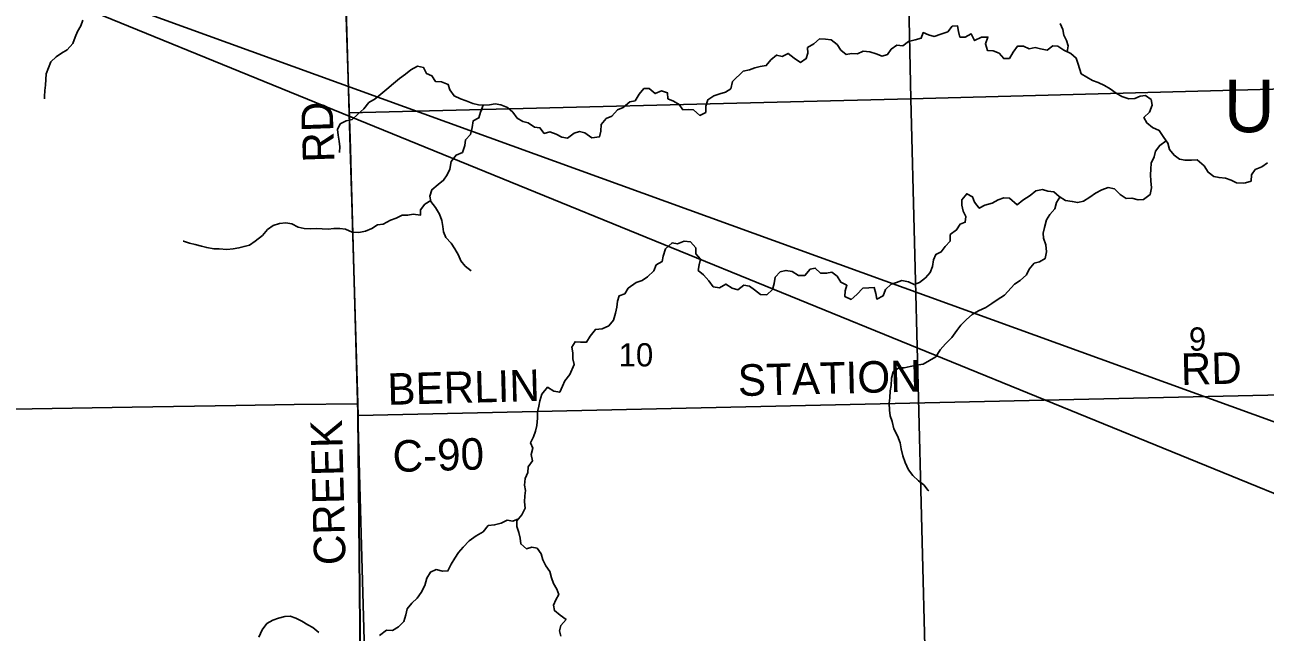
# Model space of a CAD drawing. Extents: x 0 to 34, y 0 to 22.
# Drawn here: x 6.705 to 8.938, y 16.179 to 17.274 of the extents above; entities that cross this region are included whole.
import ezdxf

# ---------------------------------------------------------------- set-up
doc = ezdxf.new("R2010")
doc.units = 0
for name, color, linetype in [('GM_X_Corporation', 7, 'Continuous'), ('GM_X_County_Road', 7, 'Continuous'), ('GM_X_County_Road_Text', 7, 'Continuous'), ('GM_X_Minor_Lake_Text', 7, 'Continuous'), ('GM_X_Minor_River', 7, 'Continuous'), ('GM_X_Section_Text', 7, 'Continuous'), ('GM_X_Township_Road', 7, 'Continuous'), ('SH_Text', 7, 'Continuous')]:
    doc.layers.add(name, color=color, linetype=linetype)

msp = doc.modelspace()

# ---------------------------------------------------------------- linework, layer by layer
at = {"layer": 'GM_X_Corporation'}
for points in [[(7.283, 17.3071), (7.2872, 17.1772), (7.2911, 17.0516), (7.2943, 16.935), (7.2998, 16.7507), (7.3046, 16.5913), (7.3049, 16.5704), (7.3097, 16.0633), (7.3129, 15.9614), (7.3375, 15.0689), (8.3803, 15.0917), (8.8365, 15.1033), (9.7895, 15.1275), (9.7895, 20.2375)], [(2.9895, 20.1176), (2.9895, 14.989), (3.1061, 14.9902), (3.7218, 15.0051), (5.1362, 15.0301), (5.7825, 15.0418), (6.0746, 15.0468), (7.3134, 15.0684), (7.3375, 15.0689), (7.3129, 15.9614), (7.3097, 16.0633), (7.3049, 16.5704), (7.3046, 16.5913), (7.2998, 16.7507), (7.2943, 16.935), (7.2911, 17.0516), (7.2872, 17.1772), (7.283, 17.3071)]]:
    msp.add_lwpolyline(points, dxfattribs=at)
for points in [[(9.2853, 18.1891), (9.3117, 17.1675), (8.3006, 17.1406), (8.2786, 18.1687)], [(8.2786, 18.1687), (8.3006, 17.1406), (7.2894, 17.115), (7.2759, 17.5735), (7.2643, 18.1469)], [(9.3117, 17.1675), (9.3404, 16.1359), (8.3266, 16.1074), (8.3006, 17.1406)], [(8.3006, 17.1406), (8.3266, 16.1074), (7.3183, 16.0795), (7.3111, 16.3358), (7.2941, 16.9623), (7.2894, 17.115)]]:
    msp.add_lwpolyline(points, close=True, dxfattribs=at)
at = {"layer": 'GM_X_County_Road'}
for points in [[(7.3099, 16.0628), (7.3051, 16.5699), (7.3048, 16.5907), (7.3, 16.7502), (7.2945, 16.9345), (7.2913, 17.051), (7.2874, 17.1766), (7.2832, 17.3066), (7.2801, 17.4169), (7.2766, 17.5196), (7.2753, 17.5759), (7.2469, 19.0552)], [(7.3051, 16.5699), (8.9434, 16.6067), (9.1022, 16.6101), (9.3888, 16.6198), (9.477, 16.6223), (9.5999, 16.6258), (9.7209, 16.6324), (9.7895, 16.6343)]]:
    msp.add_lwpolyline(points, dxfattribs=at)
at = {"layer": 'GM_X_Minor_River'}
for points in [[(6.8096, 17.2819), (6.8059, 17.2716), (6.7999, 17.2617), (6.7958, 17.2514), (6.7913, 17.2399), (6.7812, 17.2288), (6.7713, 17.2227), (6.7615, 17.2161), (6.7517, 17.2069), (6.748, 17.1959), (6.7435, 17.1852), (6.7432, 17.1753), (6.7422, 17.165), (6.7411, 17.1555), (6.7404, 17.1445), (6.7405, 17.1403)], [(8.8994, 16.9881), (8.8869, 16.9887), (8.877, 16.9935), (8.8667, 16.9976), (8.8553, 16.9983), (8.8457, 17.0005), (8.8358, 17.008), (8.8288, 17.0194), (8.8162, 17.0303), (8.8059, 17.0298), (8.7941, 17.0297), (8.7842, 17.0319), (8.7743, 17.0387), (8.7658, 17.0489), (8.7631, 17.0603), (8.7561, 17.0709), (8.7476, 17.083), (8.7354, 17.0886), (8.7251, 17.0968), (8.7201, 17.1067), (8.7299, 17.1166), (8.7347, 17.1292), (8.7331, 17.1391), (8.7231, 17.1466), (8.7132, 17.1454), (8.7034, 17.1411), (8.6928, 17.1403), (8.6805, 17.1448), (8.6698, 17.1504), (8.6595, 17.1583), (8.6488, 17.1643), (8.6374, 17.1695), (8.6274, 17.1736), (8.6068, 17.1856), (8.6017, 17.203), (8.5982, 17.2137), (8.5886, 17.2223), (8.5756, 17.2279), (8.5653, 17.2351), (8.5558, 17.2357), (8.5456, 17.2281), (8.5341, 17.2303), (8.5242, 17.2328), (8.5132, 17.2305), (8.5033, 17.235), (8.4922, 17.2352), (8.4847, 17.2245), (8.478, 17.2131), (8.4677, 17.213), (8.4593, 17.2228), (8.4486, 17.2269), (8.4387, 17.2272), (8.4348, 17.2397), (8.4392, 17.2515), (8.4278, 17.2515), (8.4153, 17.2453), (8.4091, 17.2574), (8.3985, 17.2516), (8.3887, 17.2515), (8.3863, 17.2618), (8.3843, 17.272), (8.3748, 17.2712), (8.3669, 17.2609), (8.3544, 17.257), (8.3426, 17.2527), (8.3323, 17.2556), (8.3228, 17.2597), (8.3191, 17.2495), (8.3084, 17.2467), (8.2963, 17.2439), (8.2857, 17.2359), (8.2754, 17.2369), (8.2652, 17.2296), (8.2585, 17.2201), (8.249, 17.2173), (8.2379, 17.2214), (8.2265, 17.2248), (8.2147, 17.2262), (8.2045, 17.2212), (8.1934, 17.2218), (8.1839, 17.2202), (8.1743, 17.2282), (8.1678, 17.238), (8.1567, 17.2466), (8.1468, 17.2477), (8.1358, 17.2484), (8.1256, 17.2396), (8.1146, 17.2326), (8.1151, 17.2227), (8.1121, 17.2128), (8.1015, 17.2059), (8.0904, 17.2138), (8.0797, 17.2221), (8.0687, 17.2167), (8.0588, 17.2193), (8.0486, 17.2104), (8.04, 17.2001), (8.0293, 17.1985), (8.0195, 17.1961), (8.01, 17.1926), (7.9986, 17.1899)], [(8.5816, 17.2253), (8.5835, 17.2356), (8.5804, 17.2454), (8.5757, 17.2553), (8.5741, 17.2655), (8.5691, 17.2758)], [(7.9986, 17.1899), (7.979, 17.1715), (7.9764, 17.1585), (7.9666, 17.1524), (7.9563, 17.1496), (7.9457, 17.1458), (7.9348, 17.1388), (7.9314, 17.1274), (7.9312, 17.116), (7.9206, 17.1106), (7.9091, 17.1204), (7.8995, 17.1211), (7.89, 17.1206), (7.8835, 17.1304), (7.8728, 17.1361), (7.8629, 17.1405), (7.862, 17.1512), (7.8513, 17.1549), (7.8403, 17.1499), (7.8292, 17.1589), (7.8197, 17.1592), (7.8111, 17.1485), (7.8039, 17.137), (7.7945, 17.1347), (7.7827, 17.1247), (7.7725, 17.1204), (7.7623, 17.1093), (7.7521, 17.1047), (7.7431, 17.094), (7.7424, 17.0822), (7.7399, 17.0719), (7.7262, 17.0699), (7.7135, 17.0793), (7.7036, 17.0815), (7.6942, 17.0784), (7.6821, 17.0695), (7.6722, 17.0714), (7.6618, 17.0766), (7.6504, 17.0811), (7.6405, 17.0779), (7.6325, 17.0881), (7.6229, 17.0892), (7.6111, 17.0971), (7.6015, 17.0997), (7.5916, 17.1057), (7.5835, 17.1163), (7.5739, 17.1249), (7.5621, 17.1294), (7.5522, 17.1312), (7.542, 17.1296), (7.5313, 17.1288), (7.5218, 17.1298), (7.5115, 17.132), (7.4997, 17.1365), (7.4894, 17.1402), (7.4779, 17.1458), (7.4702, 17.1564), (7.4675, 17.1659), (7.4553, 17.1711), (7.4446, 17.1714), (7.438, 17.182), (7.4285, 17.1857), (7.4231, 17.1967), (7.412, 17.1989), (7.4003, 17.1923), (7.3905, 17.1847), (7.3799, 17.177), (7.3689, 17.1678), (7.3569, 17.1578), (7.3463, 17.1486), (7.3361, 17.1405), (7.3247, 17.1336), (7.3153, 17.1221), (7.3048, 17.1129), (7.2946, 17.1033), (7.2836, 17.1006), (7.273, 17.0952), (7.2681, 17.0852), (7.2694, 17.075), (7.2713, 17.064), (7.2726, 17.0541), (7.2719, 17.0442), (7.2715, 17.0435)], [(7.5305, 17.1289), (7.5257, 17.1166), (7.5224, 17.1059), (7.5125, 17.1009), (7.5107, 17.0887), (7.5074, 17.0761), (7.4988, 17.0666), (7.4973, 17.0563), (7.4929, 17.0437), (7.4815, 17.039), (7.4725, 17.0272), (7.4703, 17.0139), (7.4655, 17.0032), (7.4591, 16.9936), (7.4493, 16.986), (7.4379, 16.9764), (7.4346, 16.9649), (7.4362, 16.9554), (7.4447, 16.9445), (7.452, 16.9324), (7.4559, 16.921), (7.4579, 16.9104), (7.4588, 16.9005), (7.4634, 16.8903), (7.473, 16.8801), (7.4792, 16.8703), (7.4861, 16.8589), (7.49, 16.8487), (7.4981, 16.8389), (7.5085, 16.8306)], [(8.7601, 17.0648), (8.7486, 17.0564), (8.7411, 17.046), (8.7382, 17.0361), (8.7333, 17.0247), (8.7323, 17.0137), (8.7316, 17.0034), (8.7325, 16.9924), (8.7337, 16.9798), (8.7312, 16.9677), (8.7194, 16.9592), (8.7096, 16.9584), (8.6985, 16.9613), (8.6882, 16.9608), (8.6775, 16.968), (8.6668, 16.9782), (8.6554, 16.9807), (8.644, 16.9761), (8.6326, 16.9703), (8.6228, 16.963), (8.6115, 16.9561), (8.6008, 16.9533), (8.5909, 16.9555), (8.5787, 16.9573), (8.5673, 16.9641), (8.5577, 16.9727), (8.547, 16.9742), (8.5375, 16.9768), (8.5253, 16.9744), (8.5151, 16.9663), (8.5023, 16.9578), (8.4917, 16.9494), (8.4779, 16.9615), (8.4676, 16.9618), (8.4578, 16.9583), (8.4468, 16.9521), (8.4339, 16.9486), (8.4237, 16.9432), (8.4152, 16.9541), (8.4113, 16.964), (8.401, 16.9692), (8.3924, 16.9585), (8.3921, 16.949), (8.3948, 16.938), (8.3995, 16.9281), (8.3984, 16.9179), (8.3889, 16.9148), (8.3826, 16.9041), (8.3709, 16.8956), (8.371, 16.8838), (8.3623, 16.8743), (8.3552, 16.8647), (8.3453, 16.8601), (8.3412, 16.8501), (8.3394, 16.8383), (8.3353, 16.8277), (8.327, 16.8181), (8.3161, 16.8093), (8.3062, 16.8058), (8.2959, 16.8106), (8.2841, 16.8128), (8.2746, 16.8097), (8.2648, 16.8066), (8.255, 16.7966), (8.2505, 16.7856), (8.2391, 16.7794), (8.2375, 16.7896), (8.2344, 16.8003), (8.2245, 16.7998), (8.2139, 16.799), (8.2033, 16.7878), (8.1927, 16.779), (8.1817, 16.7839), (8.1823, 16.7941), (8.1853, 16.8044), (8.1742, 16.81), (8.168, 16.8206), (8.1581, 16.8278), (8.1486, 16.8262), (8.1379, 16.8261), (8.1284, 16.8355), (8.1189, 16.8332), (8.1098, 16.8221), (8.0984, 16.822), (8.0866, 16.8291), (8.0755, 16.8313), (8.0653, 16.8286), (8.0562, 16.819), (8.0541, 16.8076), (8.0515, 16.7965), (8.0409, 16.7869), (8.0299, 16.788), (8.0192, 16.7959), (8.0096, 16.803), (7.9997, 16.8045), (7.9887, 16.7964), (7.9788, 16.799), (7.9673, 16.8065), (7.956, 16.7999), (7.9446, 16.8014), (7.9369, 16.8123)], [(8.9424, 17.0248), (8.9323, 17.0178), (8.9206, 17.0131), (8.914, 17.0035), (8.913, 16.9921), (8.9032, 16.9889), (8.8994, 16.9881)], [(7.4359, 16.9572), (7.4256, 16.9504), (7.4173, 16.9405), (7.4178, 16.931), (7.4041, 16.9324), (7.3946, 16.9308), (7.3843, 16.9307), (7.3737, 16.9253), (7.3635, 16.9218), (7.3506, 16.9145), (7.3404, 16.9136), (7.3302, 16.9067), (7.3184, 16.9017), (7.3066, 16.8997), (7.2948, 16.9003), (7.2823, 16.9056), (7.2724, 16.9066), (7.2617, 16.9069), (7.2514, 16.9053), (7.2404, 16.9064), (7.2301, 16.907), (7.2187, 16.9062), (7.2081, 16.9065), (7.197, 16.9094), (7.1859, 16.9151), (7.1749, 16.9169), (7.1635, 16.916), (7.1525, 16.9121), (7.1423, 16.9048), (7.1329, 16.8941), (7.1197, 16.8837), (7.1095, 16.8768), (7.1, 16.8745), (7.0905, 16.8717), (7.0802, 16.8701), (7.0688, 16.8689), (7.0551, 16.8699), (7.0456, 16.8702), (7.0327, 16.8724), (7.0231, 16.875), (7.0121, 16.8779), (7.0014, 16.8805), (6.9907, 16.8838), (6.99, 16.8838)], [(8.5685, 16.9633), (8.5624, 16.9534), (8.5595, 16.9423), (8.5508, 16.932), (8.5448, 16.9221), (8.5408, 16.9084), (8.5386, 16.8985), (8.539, 16.889), (8.5437, 16.8772), (8.5446, 16.8647), (8.542, 16.8525), (8.5322, 16.8467), (8.5227, 16.844), (8.5137, 16.8336), (8.5088, 16.8233), (8.4971, 16.813), (8.4869, 16.8064), (8.4688, 16.7865), (8.4559, 16.7781), (8.4461, 16.7715), (8.4355, 16.7646), (8.4223, 16.7584), (8.4109, 16.7515), (8.4004, 16.7427), (8.3902, 16.7323), (8.3834, 16.7228), (8.374, 16.7101), (8.3627, 16.6987), (8.3529, 16.6883), (8.3454, 16.6757), (8.3337, 16.6688), (8.3223, 16.6622), (8.3106, 16.6606), (8.2992, 16.6582), (8.2882, 16.6559), (8.2787, 16.6554), (8.2688, 16.6485), (8.2655, 16.6371), (8.2649, 16.6238), (8.263, 16.6142), (8.2628, 16.6017), (8.2613, 16.5922), (8.2618, 16.5793), (8.2634, 16.569), (8.2666, 16.5588), (8.2697, 16.5459), (8.2763, 16.5334), (8.2814, 16.5205), (8.283, 16.5099), (8.2857, 16.497), (8.2904, 16.4852), (8.2962, 16.472), (8.3039, 16.4614), (8.3139, 16.4523), (8.3235, 16.4448), (8.3316, 16.4346), (8.3319, 16.4361)], [(7.9369, 16.8123), (7.9269, 16.8233), (7.9173, 16.8312), (7.9195, 16.8415), (7.9217, 16.8514), (7.9132, 16.8612), (7.9131, 16.8718), (7.9039, 16.8824), (7.8925, 16.8838), (7.8804, 16.8788), (7.8705, 16.881), (7.8588, 16.8699), (7.8543, 16.8569), (7.8525, 16.847), (7.8419, 16.8412), (7.8374, 16.8302), (7.8265, 16.8194), (7.8167, 16.8133), (7.8061, 16.8094), (7.7917, 16.799), (7.7853, 16.7891), (7.7751, 16.7856), (7.7725, 16.7757), (7.7711, 16.765), (7.7689, 16.7544), (7.7652, 16.7414), (7.7565, 16.7311), (7.7448, 16.726), (7.7326, 16.7248), (7.7232, 16.7126), (7.7165, 16.7022), (7.7058, 16.7022), (7.6959, 16.7028), (7.6899, 16.6929), (7.6916, 16.6827), (7.692, 16.672), (7.6944, 16.6618), (7.6866, 16.6435), (7.6775, 16.6324), (7.6734, 16.6225), (7.6682, 16.6118), (7.6575, 16.6136), (7.6465, 16.6207), (7.6363, 16.6085), (7.6322, 16.5959), (7.6304, 16.5864), (7.6282, 16.5761), (7.6283, 16.5647), (7.6269, 16.5518), (7.6243, 16.5415), (7.621, 16.5316), (7.6158, 16.5205), (7.6197, 16.5107), (7.6167, 16.4996), (7.6191, 16.4879), (7.6116, 16.4772), (7.6105, 16.4669), (7.6057, 16.4562), (7.6047, 16.444), (7.6063, 16.4345), (7.6056, 16.425), (7.6045, 16.4144), (7.6058, 16.403), (7.5998, 16.3908), (7.5911, 16.3801), (7.5909, 16.3698), (7.5947, 16.3592), (7.5967, 16.3486), (7.598, 16.3383), (7.6083, 16.3296), (7.6178, 16.3324), (7.6273, 16.3309), (7.6346, 16.3207), (7.6378, 16.3097), (7.6432, 16.2988), (7.6505, 16.2886), (7.6533, 16.2772), (7.6568, 16.2673), (7.663, 16.2571), (7.6665, 16.2472), (7.6612, 16.2377), (7.6568, 16.2278), (7.6587, 16.2183), (7.6691, 16.21), (7.6798, 16.2021), (7.6704, 16.1914), (7.6678, 16.1819), (7.6702, 16.172)], [(7.5941, 16.3837), (7.5839, 16.3792), (7.5736, 16.3811), (7.563, 16.376), (7.5509, 16.3725), (7.5395, 16.3717), (7.5305, 16.3602), (7.518, 16.3529), (7.5051, 16.344), (7.4942, 16.3325), (7.4859, 16.323), (7.4795, 16.313), (7.4728, 16.302), (7.4668, 16.2897), (7.4573, 16.2893), (7.4459, 16.2922), (7.4356, 16.2876), (7.4289, 16.2765), (7.4256, 16.2636), (7.4188, 16.251), (7.4117, 16.2407), (7.4019, 16.2318), (7.3936, 16.2215), (7.3911, 16.2105), (7.3874, 16.1986), (7.3779, 16.1887), (7.3673, 16.1825), (7.3563, 16.1828), (7.3438, 16.1732)], [(7.2346, 16.1788), (7.2239, 16.1878), (7.2144, 16.1923), (7.2037, 16.1991), (7.1933, 16.2047), (7.183, 16.2084), (7.1732, 16.2076), (7.1621, 16.2048), (7.1515, 16.2009), (7.1406, 16.1948), (7.1323, 16.1833), (7.1263, 16.1703)]]:
    msp.add_lwpolyline(points, dxfattribs=at)
at = {"layer": 'GM_X_Township_Road'}
msp.add_lwpolyline([(6.6457, 16.5804), (6.8983, 16.5849), (7.0851, 16.5879), (7.1901, 16.5898), (7.3048, 16.5907)], dxfattribs=at)
at = {"layer": 'SH_Text'}
msp.add_lwpolyline([(11.7478, 15.5458), (6.1293, 17.5829), (11.7478, 15.2891)], close=True, dxfattribs=at)

# ---------------------------------------------------------------- texts
at = {"layer": 'GM_X_County_Road_Text'}
for s, rotation, p in [('RD', 91.9757, (7.2628, 17.0266)), ('RD', 1.4806, (8.7871, 16.6247)), ('STATION', 1.4486, (7.9896, 16.6047)), ('BERLIN', 1.5223, (7.3587, 16.5888)), ('CREEK', 91.4688, (7.2828, 16.3009)), ('C-90', 1.714, (7.3681, 16.4678))]:
    msp.add_text(s, height=0.05682, rotation=rotation, dxfattribs=at).set_placement(p)
at = {"layer": 'GM_X_Minor_Lake_Text'}
msp.add_text('Upper Diehl', height=0.094732, rotation=359.9569, dxfattribs=at).set_placement((8.8639, 17.0802))
at = {"layer": 'GM_X_Section_Text'}
for s, height, p in [('9', 0.0419, (8.801, 16.6866)), ('10', 0.04186, (7.7743, 16.6582))]:
    msp.add_text(s, height=height, rotation=0, dxfattribs=at).set_placement(p)

doc.saveas('drawing.dxf')
